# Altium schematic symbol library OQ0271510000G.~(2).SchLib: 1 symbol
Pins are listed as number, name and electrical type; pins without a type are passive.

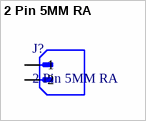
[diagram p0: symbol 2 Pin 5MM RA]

## 2 Pin 5MM RA
designator J?
2 Pin Terminal Block HDR 5MM THT RA _OQ0271510000G; MF: Amphenol Anytek
footprint AMPHENOL_OQ0271510000G
pins: 1, 2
